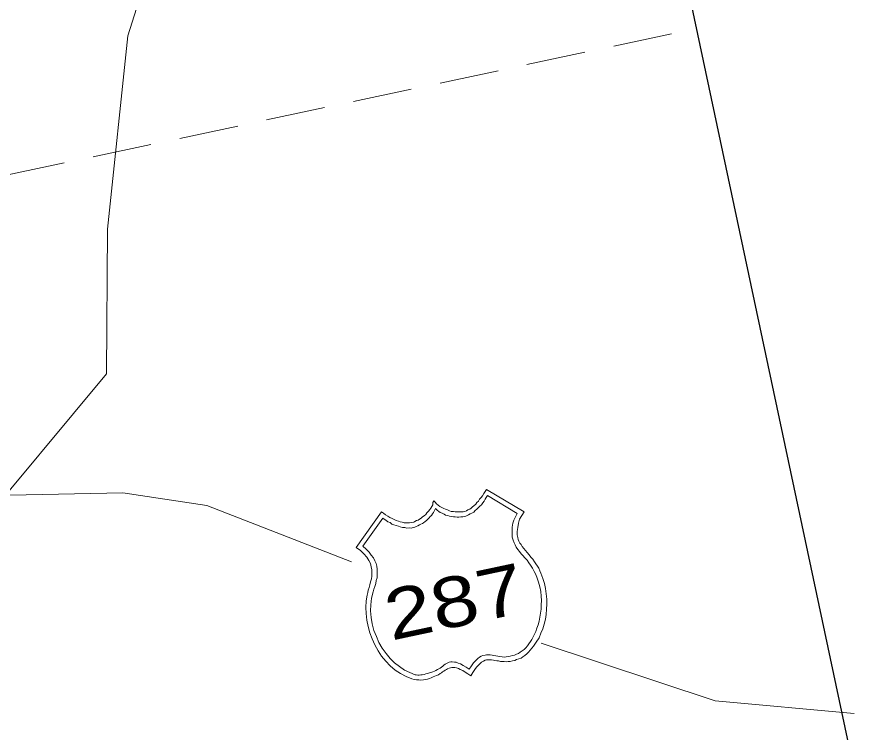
# Model space of a CAD drawing. Extents: x 2357218 to 2371708, y 6973728 to 6980157.
# Drawn here: x 2371620.9 to 2371708, y 6977470 to 6977542.6 of the extents above; entities that cross this region are included whole.
import ezdxf

# ---------------------------------------------------------------- set-up
doc = ezdxf.new("R2010")
doc.units = 0
doc.header["$LTSCALE"] = 2
doc.linetypes.add('MEDIUM_DASHED', pattern=[4.5, 3, -1.5])
doc.layers.add('62', color=7, linetype='Continuous', lineweight=13)
doc.layers.add('63', color=7, linetype='Continuous', lineweight=13)

msp = doc.modelspace()

# ---------------------------------------------------------------- linework, layer by layer
at = {"layer": '62', "linetype": 'MEDIUM_DASHED'}
msp.add_line((2371250.037, 6977447.964), (2371689.806, 6977541.441), dxfattribs=at)
at = {"layer": '62'}
for p, q in [((2371640.114, 6977493.057), (2371654.81, 6977487.347)), ((2371691.688, 6977473.263), (2371674.044, 6977479.105)), ((2371705.79, 6977471.978), (2371691.688, 6977473.263))]:
    msp.add_line(p, q, dxfattribs=at)
at = {"layer": '62', "lineweight": 25}
msp.add_lwpolyline([(2371171.482, 6977817.538), (2371268.218, 6977362.432), (2371707.985, 6977455.907), (2371611.249, 6977911.015)], dxfattribs=at)
at = {"layer": '62'}
for points in [[(2371640.114, 6977493.057), (2371631.587, 6977494.329), (2371621.782, 6977494.129), (2371604.117, 6977494.011), (2371592.783, 6977497.996), (2371585.105, 6977500.871), (2371575.158, 6977504.807), (2371564.602, 6977512.159), (2371556.475, 6977520.853), (2371548.287, 6977530.798), (2371537.195, 6977542.291), (2371528.149, 6977549.131), (2371520.811, 6977556.266), (2371512.448, 6977565.414), (2371507.538, 6977569.364), (2371497.978, 6977580.353)], [(2371641.471, 6977568.825), (2371637.889, 6977558.952), (2371632.104, 6977540.699), (2371630.059, 6977521.101), (2371629.958, 6977506.428), (2371616.354, 6977490.125), (2371618.311, 6977480.254), (2371604.289, 6977467.66), (2371593.247, 6977456.295), (2371579.034, 6977445.889), (2371557.99, 6977437.089), (2371540.234, 6977428.852), (2371521.019, 6977419.249), (2371509.386, 6977413.693)], [(2371655.262, 6977488.799), (2371657.829, 6977492.405), (2371658.044, 6977492.267), (2371658.26, 6977492.105), (2371658.491, 6977491.993), (2371658.683, 6977491.849), (2371658.917, 6977491.74), (2371659.119, 6977491.643), (2371659.323, 6977491.55), (2371659.549, 6977491.459), (2371659.722, 6977491.403), (2371659.938, 6977491.358), (2371660.133, 6977491.306), (2371660.342, 6977491.304), (2371660.528, 6977491.298), (2371660.689, 6977491.289), (2371660.911, 6977491.333), (2371661.108, 6977491.375), (2371661.232, 6977491.449), (2371661.375, 6977491.526), (2371661.546, 6977491.585), (2371661.708, 6977491.689), (2371661.872, 6977491.792), (2371662.006, 6977491.913), (2371662.17, 6977492.016), (2371662.326, 6977492.14), (2371662.452, 6977492.305), (2371662.6, 6977492.474), (2371662.727, 6977492.639), (2371662.856, 6977492.781), (2371662.934, 6977492.962), (2371663.033, 6977493.142), (2371663.058, 6977493.354), (2371663.134, 6977493.532), (2371663.276, 6977493.402), (2371663.43, 6977493.227), (2371663.598, 6977493.079), (2371663.76, 6977492.973), (2371663.947, 6977492.853), (2371664.149, 6977492.758), (2371664.327, 6977492.682), (2371664.527, 6977492.608), (2371664.724, 6977492.536), (2371664.904, 6977492.46), (2371665.133, 6977492.461), (2371665.308, 6977492.407), (2371665.558, 6977492.413), (2371665.722, 6977492.403), (2371665.95, 6977492.404), (2371666.133, 6977492.421), (2371666.285, 6977492.454), (2371666.478, 6977492.519), (2371666.597, 6977492.611), (2371666.784, 6977492.696), (2371666.947, 6977492.802), (2371667.083, 6977492.923), (2371667.219, 6977493.042), (2371667.393, 6977493.196), (2371667.52, 6977493.361), (2371667.671, 6977493.506), (2371667.792, 6977493.695), (2371667.962, 6977493.869), (2371668.086, 6977494.054), (2371668.222, 6977494.27), (2371668.339, 6977494.478), (2371668.483, 6977494.669), (2371672.298, 6977492.42), (2371672.076, 6977492.05), (2371671.855, 6977491.682), (2371671.735, 6977491.266), (2371671.667, 6977490.838), (2371671.592, 6977490.429), (2371671.594, 6977490.085), (2371671.656, 6977489.8), (2371671.698, 6977489.602), (2371671.781, 6977489.434), (2371671.889, 6977489.252), (2371671.992, 6977489.088), (2371672.126, 6977488.888), (2371672.282, 6977488.692), (2371672.441, 6977488.494), (2371672.625, 6977488.281), (2371672.808, 6977488.067), (2371672.995, 6977487.829), (2371673.18, 6977487.617), (2371673.35, 6977487.353), (2371673.511, 6977487.133), (2371673.651, 6977486.91), (2371673.79, 6977486.688), (2371673.913, 6977486.438), (2371674.007, 6977486.206), (2371674.191, 6977485.669), (2371674.376, 6977485.132), (2371674.482, 6977484.626), (2371674.527, 6977484.085), (2371674.597, 6977483.548), (2371674.612, 6977483.043), (2371674.582, 6977482.531), (2371674.53, 6977482.015), (2371674.475, 6977481.521), (2371674.353, 6977481.01)], [(2371673.346, 6977480.015), (2371673.497, 6977480.276), (2371673.609, 6977480.623), (2371673.718, 6977480.967), (2371673.824, 6977481.336), (2371673.903, 6977481.72), (2371673.978, 6977482.127), (2371674.032, 6977482.529), (2371674.05, 6977482.971), (2371674.069, 6977483.434), (2371674.023, 6977483.862), (2371673.989, 6977484.338), (2371673.894, 6977484.802), (2371673.768, 6977485.279), (2371673.634, 6977485.689), (2371673.507, 6977486.075), (2371673.328, 6977486.382), (2371673.163, 6977486.715), (2371672.966, 6977486.997), (2371672.796, 6977487.259), (2371672.602, 6977487.517), (2371672.391, 6977487.747), (2371672.182, 6977487.979), (2371672.002, 6977488.172), (2371671.841, 6977488.391), (2371671.681, 6977488.609), (2371671.513, 6977488.848), (2371671.402, 6977489.055), (2371671.283, 6977489.284), (2371671.182, 6977489.539), (2371671.095, 6977489.842), (2371671.092, 6977490.187), (2371671.088, 6977490.531), (2371671.106, 6977490.879), (2371671.162, 6977491.258), (2371671.277, 6977491.583), (2371671.438, 6977491.917), (2371671.596, 6977492.249), (2371668.587, 6977494.071), (2371668.468, 6977493.884), (2371668.366, 6977493.7), (2371668.25, 6977493.492), (2371668.124, 6977493.327), (2371667.982, 6977493.137), (2371667.828, 6977492.99), (2371667.677, 6977492.842), (2371667.522, 6977492.694), (2371667.348, 6977492.542), (2371667.195, 6977492.395), (2371667.01, 6977492.286), (2371666.845, 6977492.205), (2371666.681, 6977492.1), (2371666.533, 6977492.047), (2371666.385, 6977491.992), (2371666.234, 6977491.935), (2371666.076, 6977491.926), (2371665.894, 6977491.911), (2371665.698, 6977491.868), (2371665.532, 6977491.88), (2371665.299, 6977491.9), (2371665.135, 6977491.91), (2371664.945, 6977491.939), (2371664.729, 6977491.983), (2371664.555, 6977492.04), (2371664.339, 6977492.086), (2371664.185, 6977492.167), (2371664.002, 6977492.268), (2371663.803, 6977492.34), (2371663.639, 6977492.467), (2371663.473, 6977492.591), (2371663.304, 6977492.741), (2371663.204, 6977492.559), (2371663.11, 6977492.355), (2371663.001, 6977492.216), (2371662.896, 6977492.056), (2371662.762, 6977491.935), (2371662.674, 6977491.802), (2371662.521, 6977491.653), (2371662.409, 6977491.538), (2371662.269, 6977491.438), (2371662.111, 6977491.312), (2371661.988, 6977491.24), (2371661.822, 6977491.161), (2371661.678, 6977491.083), (2371661.537, 6977490.984), (2371661.361, 6977490.947), (2371661.218, 6977490.871), (2371661.066, 6977490.814), (2371660.847, 6977490.77), (2371660.635, 6977490.793), (2371660.409, 6977490.769), (2371660.214, 6977490.819), (2371659.98, 6977490.837), (2371659.744, 6977490.88), (2371659.564, 6977490.957), (2371659.321, 6977491.02), (2371659.096, 6977491.11), (2371658.896, 6977491.183), (2371658.702, 6977491.327), (2371658.479, 6977491.415), (2371658.285, 6977491.558)], [(2371657.966, 6977491.767), (2371655.947, 6977488.923), (2371656.287, 6977488.625), (2371656.581, 6977488.319), (2371656.805, 6977488.023), (2371657.025, 6977487.749), (2371657.16, 6977487.432), (2371657.287, 6977487.161), (2371657.365, 6977486.901), (2371657.411, 6977486.588), (2371657.406, 6977486.286), (2371657.416, 6977486.014), (2371657.385, 6977485.73), (2371657.308, 6977485.437), (2371657.256, 6977485.152), (2371657.179, 6977484.86), (2371657.078, 6977484.584), (2371656.978, 6977484.288), (2371656.813, 6977483.656), (2371656.747, 6977482.995), (2371656.719, 6977482.37), (2371656.793, 6977481.695), (2371656.907, 6977481.052), (2371657.068, 6977480.397), (2371657.319, 6977479.759), (2371657.583, 6977479.172), (2371657.911, 6977478.597), (2371658.306, 6977478.037), (2371658.733, 6977477.551), (2371659.175, 6977477.093), (2371659.668, 6977476.718), (2371660.181, 6977476.366), (2371660.718, 6977476.11), (2371661.245, 6977475.901), (2371661.363, 6977475.882), (2371661.511, 6977475.841), (2371661.669, 6977475.855), (2371661.846, 6977475.892), (2371661.981, 6977475.898), (2371662.16, 6977475.934), (2371662.336, 6977475.972), (2371662.512, 6977476.009), (2371662.705, 6977476.073), (2371662.859, 6977476.108), (2371663.046, 6977476.191), (2371663.219, 6977476.253), (2371663.364, 6977476.327), (2371663.531, 6977476.41), (2371663.671, 6977476.509), (2371663.797, 6977476.56), (2371663.912, 6977476.675), (2371664.05, 6977476.776), (2371664.148, 6977476.862), (2371664.286, 6977476.963), (2371664.432, 6977477.039), (2371664.56, 6977477.089), (2371664.704, 6977477.164), (2371664.858, 6977477.199), (2371665.022, 6977477.188), (2371665.23, 6977477.186), (2371665.414, 6977477.179), (2371665.616, 6977477.084), (2371665.867, 6977477), (2371666.133, 6977476.826), (2371666.444, 6977476.662), (2371666.743, 6977476.449), (2371666.967, 6977476.797), (2371667.18, 6977477.095), (2371667.384, 6977477.321), (2371667.595, 6977477.527), (2371667.769, 6977477.68), (2371667.958, 6977477.766), (2371668.124, 6977477.847), (2371668.345, 6977477.894), (2371668.5, 6977477.927), (2371668.662, 6977477.916), (2371668.869, 6977477.914), (2371669.059, 6977477.885), (2371669.234, 6977477.831), (2371669.422, 6977477.803), (2371669.634, 6977477.776), (2371669.852, 6977477.73), (2371670.064, 6977477.707), (2371670.273, 6977477.684), (2371670.478, 6977477.702), (2371670.699, 6977477.75), (2371670.903, 6977477.77), (2371671.118, 6977477.838), (2371671.315, 6977477.881), (2371671.525, 6977477.972), (2371671.737, 6977478.062), (2371671.92, 6977478.171), (2371672.118, 6977478.327), (2371672.296, 6977478.458), (2371672.466, 6977478.632), (2371672.659, 6977478.81), (2371672.798, 6977479.025), (2371672.953, 6977479.265), (2371673.097, 6977479.455), (2371673.221, 6977479.735), (2371673.346, 6977480.015)], [(2371658.285, 6977491.558), (2371658.126, 6977491.661), (2371657.966, 6977491.767)], [(2371656.062, 6977488.164), (2371655.718, 6977488.481), (2371655.262, 6977488.799)], [(2371674.353, 6977481.01), (2371674.199, 6977480.542), (2371673.993, 6977480.107), (2371673.818, 6977479.631), (2371673.517, 6977479.201), (2371673.263, 6977478.777), (2371672.934, 6977478.385), (2371672.745, 6977478.184), (2371672.577, 6977478.012), (2371672.378, 6977477.855), (2371672.177, 6977477.72), (2371671.999, 6977477.588), (2371671.782, 6977477.521), (2371671.549, 6977477.423), (2371671.363, 6977477.34), (2371671.118, 6977477.288), (2371670.897, 6977477.241), (2371670.697, 6977477.221), (2371670.516, 6977477.206), (2371670.283, 6977477.226), (2371670.096, 6977477.231), (2371669.91, 6977477.236), (2371669.715, 6977477.289), (2371669.527, 6977477.317), (2371669.335, 6977477.344), (2371669.19, 6977477.384), (2371669, 6977477.411), (2371668.862, 6977477.406), (2371668.677, 6977477.413), (2371668.493, 6977477.42), (2371668.342, 6977477.363), (2371668.175, 6977477.282), (2371667.991, 6977477.175), (2371667.839, 6977477.027), (2371667.664, 6977476.875), (2371667.476, 6977476.674), (2371667.299, 6977476.43), (2371667.113, 6977476.114), (2371666.909, 6977475.772), (2371666.587, 6977475.98), (2371666.323, 6977476.153), (2371666.077, 6977476.331), (2371665.825, 6977476.438), (2371665.643, 6977476.536), (2371665.448, 6977476.586), (2371665.279, 6977476.622), (2371665.117, 6977476.632), (2371664.979, 6977476.627), (2371664.825, 6977476.593), (2371664.694, 6977476.565), (2371664.55, 6977476.49), (2371664.45, 6977476.422), (2371664.299, 6977476.367), (2371664.165, 6977476.246), (2371664.041, 6977476.175), (2371663.924, 6977476.08), (2371663.779, 6977476.003), (2371663.617, 6977475.901), (2371663.427, 6977475.813), (2371663.26, 6977475.733), (2371663.067, 6977475.668), (2371662.879, 6977475.58), (2371662.714, 6977475.5), (2371662.493, 6977475.454), (2371662.293, 6977475.412), (2371662.094, 6977475.368), (2371661.844, 6977475.36), (2371661.635, 6977475.363), (2371661.402, 6977475.383), (2371661.164, 6977475.424), (2371660.919, 6977475.488), (2371660.343, 6977475.71), (2371659.769, 6977476.025), (2371659.213, 6977476.367), (2371658.732, 6977476.795), (2371658.263, 6977477.267), (2371657.856, 6977477.781), (2371657.51, 6977478.328), (2371657.175, 6977478.924), (2371656.885, 6977479.528), (2371656.661, 6977480.149), (2371656.478, 6977480.8), (2371656.34, 6977481.439), (2371656.271, 6977482.093), (2371656.252, 6977482.729), (2371656.297, 6977483.384), (2371656.399, 6977483.981), (2371656.44, 6977484.22), (2371656.498, 6977484.485), (2371656.584, 6977484.734), (2371656.66, 6977485.024), (2371656.739, 6977485.316), (2371656.812, 6977485.608), (2371656.867, 6977485.898), (2371656.871, 6977486.196), (2371656.872, 6977486.518), (2371656.803, 6977486.85), (2371656.71, 6977487.174), (2371656.551, 6977487.487), (2371656.341, 6977487.833), (2371656.062, 6977488.164)]]:
    msp.add_lwpolyline(points, dxfattribs=at)
at = {"layer": '63', "linetype": 'MEDIUM_DASHED'}
msp.add_line((2371250.037, 6977447.964), (2371689.806, 6977541.441), dxfattribs=at)
at = {"layer": '63'}
for p, q in [((2371640.114, 6977493.057), (2371654.81, 6977487.347)), ((2371691.688, 6977473.263), (2371674.044, 6977479.105)), ((2371705.79, 6977471.978), (2371691.688, 6977473.263))]:
    msp.add_line(p, q, dxfattribs=at)
at = {"layer": '63', "lineweight": 25}
msp.add_lwpolyline([(2371171.482, 6977817.538), (2371268.218, 6977362.432), (2371707.985, 6977455.907), (2371611.249, 6977911.015)], dxfattribs=at)
at = {"layer": '63'}
for points in [[(2371640.114, 6977493.057), (2371631.587, 6977494.329), (2371621.782, 6977494.129), (2371604.117, 6977494.011), (2371592.783, 6977497.996), (2371585.105, 6977500.871), (2371575.158, 6977504.807), (2371564.602, 6977512.159), (2371556.475, 6977520.853), (2371548.287, 6977530.798), (2371537.195, 6977542.291), (2371528.149, 6977549.131), (2371520.811, 6977556.266), (2371512.448, 6977565.414), (2371507.538, 6977569.364), (2371497.978, 6977580.353)], [(2371641.471, 6977568.825), (2371637.889, 6977558.952), (2371632.104, 6977540.699), (2371630.059, 6977521.101), (2371629.958, 6977506.428), (2371616.354, 6977490.125), (2371618.311, 6977480.254), (2371604.289, 6977467.66), (2371593.247, 6977456.295), (2371579.034, 6977445.889), (2371557.99, 6977437.089), (2371540.234, 6977428.852), (2371521.019, 6977419.249), (2371509.386, 6977413.693)], [(2371655.262, 6977488.799), (2371657.829, 6977492.405), (2371658.044, 6977492.267), (2371658.26, 6977492.105), (2371658.491, 6977491.993), (2371658.683, 6977491.849), (2371658.917, 6977491.74), (2371659.119, 6977491.643), (2371659.323, 6977491.55), (2371659.549, 6977491.459), (2371659.722, 6977491.403), (2371659.938, 6977491.358), (2371660.133, 6977491.306), (2371660.342, 6977491.304), (2371660.528, 6977491.298), (2371660.689, 6977491.289), (2371660.911, 6977491.333), (2371661.108, 6977491.375), (2371661.232, 6977491.449), (2371661.375, 6977491.526), (2371661.546, 6977491.585), (2371661.708, 6977491.689), (2371661.872, 6977491.792), (2371662.006, 6977491.913), (2371662.17, 6977492.016), (2371662.326, 6977492.14), (2371662.452, 6977492.305), (2371662.6, 6977492.474), (2371662.727, 6977492.639), (2371662.856, 6977492.781), (2371662.934, 6977492.962), (2371663.033, 6977493.142), (2371663.058, 6977493.354), (2371663.134, 6977493.532), (2371663.276, 6977493.402), (2371663.43, 6977493.227), (2371663.598, 6977493.079), (2371663.76, 6977492.973), (2371663.947, 6977492.853), (2371664.149, 6977492.758), (2371664.327, 6977492.682), (2371664.527, 6977492.608), (2371664.724, 6977492.536), (2371664.904, 6977492.46), (2371665.133, 6977492.461), (2371665.308, 6977492.407), (2371665.558, 6977492.413), (2371665.722, 6977492.403), (2371665.95, 6977492.404), (2371666.133, 6977492.421), (2371666.285, 6977492.454), (2371666.478, 6977492.519), (2371666.597, 6977492.611), (2371666.784, 6977492.696), (2371666.947, 6977492.802), (2371667.083, 6977492.923), (2371667.219, 6977493.042), (2371667.393, 6977493.196), (2371667.52, 6977493.361), (2371667.671, 6977493.506), (2371667.792, 6977493.695), (2371667.962, 6977493.869), (2371668.086, 6977494.054), (2371668.222, 6977494.27), (2371668.339, 6977494.478), (2371668.483, 6977494.669), (2371672.298, 6977492.42), (2371672.076, 6977492.05), (2371671.855, 6977491.682), (2371671.735, 6977491.266), (2371671.667, 6977490.838), (2371671.592, 6977490.429), (2371671.594, 6977490.085), (2371671.656, 6977489.8), (2371671.698, 6977489.602), (2371671.781, 6977489.434), (2371671.889, 6977489.252), (2371671.992, 6977489.088), (2371672.126, 6977488.888), (2371672.282, 6977488.692), (2371672.441, 6977488.494), (2371672.625, 6977488.281), (2371672.808, 6977488.067), (2371672.995, 6977487.829), (2371673.18, 6977487.617), (2371673.35, 6977487.353), (2371673.511, 6977487.133), (2371673.651, 6977486.91), (2371673.79, 6977486.688), (2371673.913, 6977486.438), (2371674.007, 6977486.206), (2371674.191, 6977485.669), (2371674.376, 6977485.132), (2371674.482, 6977484.626), (2371674.527, 6977484.085), (2371674.597, 6977483.548), (2371674.612, 6977483.043), (2371674.582, 6977482.531), (2371674.53, 6977482.015), (2371674.475, 6977481.521), (2371674.353, 6977481.01)], [(2371673.346, 6977480.015), (2371673.497, 6977480.276), (2371673.609, 6977480.623), (2371673.718, 6977480.967), (2371673.824, 6977481.336), (2371673.903, 6977481.72), (2371673.978, 6977482.127), (2371674.032, 6977482.529), (2371674.05, 6977482.971), (2371674.069, 6977483.434), (2371674.023, 6977483.862), (2371673.989, 6977484.338), (2371673.894, 6977484.802), (2371673.768, 6977485.279), (2371673.634, 6977485.689), (2371673.507, 6977486.075), (2371673.328, 6977486.382), (2371673.163, 6977486.715), (2371672.966, 6977486.997), (2371672.796, 6977487.259), (2371672.602, 6977487.517), (2371672.391, 6977487.747), (2371672.182, 6977487.979), (2371672.002, 6977488.172), (2371671.841, 6977488.391), (2371671.681, 6977488.609), (2371671.513, 6977488.848), (2371671.402, 6977489.055), (2371671.283, 6977489.284), (2371671.182, 6977489.539), (2371671.095, 6977489.842), (2371671.092, 6977490.187), (2371671.088, 6977490.531), (2371671.106, 6977490.879), (2371671.162, 6977491.258), (2371671.277, 6977491.583), (2371671.438, 6977491.917), (2371671.596, 6977492.249), (2371668.587, 6977494.071), (2371668.468, 6977493.884), (2371668.366, 6977493.7), (2371668.25, 6977493.492), (2371668.124, 6977493.327), (2371667.982, 6977493.137), (2371667.828, 6977492.99), (2371667.677, 6977492.842), (2371667.522, 6977492.694), (2371667.348, 6977492.542), (2371667.195, 6977492.395), (2371667.01, 6977492.286), (2371666.845, 6977492.205), (2371666.681, 6977492.1), (2371666.533, 6977492.047), (2371666.385, 6977491.992), (2371666.234, 6977491.935), (2371666.076, 6977491.926), (2371665.894, 6977491.911), (2371665.698, 6977491.868), (2371665.532, 6977491.88), (2371665.299, 6977491.9), (2371665.135, 6977491.91), (2371664.945, 6977491.939), (2371664.729, 6977491.983), (2371664.555, 6977492.04), (2371664.339, 6977492.086), (2371664.185, 6977492.167), (2371664.002, 6977492.268), (2371663.803, 6977492.34), (2371663.639, 6977492.467), (2371663.473, 6977492.591), (2371663.304, 6977492.741), (2371663.204, 6977492.559), (2371663.11, 6977492.355), (2371663.001, 6977492.216), (2371662.896, 6977492.056), (2371662.762, 6977491.935), (2371662.674, 6977491.802), (2371662.521, 6977491.653), (2371662.409, 6977491.538), (2371662.269, 6977491.438), (2371662.111, 6977491.312), (2371661.988, 6977491.24), (2371661.822, 6977491.161), (2371661.678, 6977491.083), (2371661.537, 6977490.984), (2371661.361, 6977490.947), (2371661.218, 6977490.871), (2371661.066, 6977490.814), (2371660.847, 6977490.77), (2371660.635, 6977490.793), (2371660.409, 6977490.769), (2371660.214, 6977490.819), (2371659.98, 6977490.837), (2371659.744, 6977490.88), (2371659.564, 6977490.957), (2371659.321, 6977491.02), (2371659.096, 6977491.11), (2371658.896, 6977491.183), (2371658.702, 6977491.327), (2371658.479, 6977491.415), (2371658.285, 6977491.558)], [(2371657.966, 6977491.767), (2371655.947, 6977488.923), (2371656.287, 6977488.625), (2371656.581, 6977488.319), (2371656.805, 6977488.023), (2371657.025, 6977487.749), (2371657.16, 6977487.432), (2371657.287, 6977487.161), (2371657.365, 6977486.901), (2371657.411, 6977486.588), (2371657.406, 6977486.286), (2371657.416, 6977486.014), (2371657.385, 6977485.73), (2371657.308, 6977485.437), (2371657.256, 6977485.152), (2371657.179, 6977484.86), (2371657.078, 6977484.584), (2371656.978, 6977484.288), (2371656.813, 6977483.656), (2371656.747, 6977482.995), (2371656.719, 6977482.37), (2371656.793, 6977481.695), (2371656.907, 6977481.052), (2371657.068, 6977480.397), (2371657.319, 6977479.759), (2371657.583, 6977479.172), (2371657.911, 6977478.597), (2371658.306, 6977478.037), (2371658.733, 6977477.551), (2371659.175, 6977477.093), (2371659.668, 6977476.718), (2371660.181, 6977476.366), (2371660.718, 6977476.11), (2371661.245, 6977475.901), (2371661.363, 6977475.882), (2371661.511, 6977475.841), (2371661.669, 6977475.855), (2371661.846, 6977475.892), (2371661.981, 6977475.898), (2371662.16, 6977475.934), (2371662.336, 6977475.972), (2371662.512, 6977476.009), (2371662.705, 6977476.073), (2371662.859, 6977476.108), (2371663.046, 6977476.191), (2371663.219, 6977476.253), (2371663.364, 6977476.327), (2371663.531, 6977476.41), (2371663.671, 6977476.509), (2371663.797, 6977476.56), (2371663.912, 6977476.675), (2371664.05, 6977476.776), (2371664.148, 6977476.862), (2371664.286, 6977476.963), (2371664.432, 6977477.039), (2371664.56, 6977477.089), (2371664.704, 6977477.164), (2371664.858, 6977477.199), (2371665.022, 6977477.188), (2371665.23, 6977477.186), (2371665.414, 6977477.179), (2371665.616, 6977477.084), (2371665.867, 6977477), (2371666.133, 6977476.826), (2371666.444, 6977476.662), (2371666.743, 6977476.449), (2371666.967, 6977476.797), (2371667.18, 6977477.095), (2371667.384, 6977477.321), (2371667.595, 6977477.527), (2371667.769, 6977477.68), (2371667.958, 6977477.766), (2371668.124, 6977477.847), (2371668.345, 6977477.894), (2371668.5, 6977477.927), (2371668.662, 6977477.916), (2371668.869, 6977477.914), (2371669.059, 6977477.885), (2371669.234, 6977477.831), (2371669.422, 6977477.803), (2371669.634, 6977477.776), (2371669.852, 6977477.73), (2371670.064, 6977477.707), (2371670.273, 6977477.684), (2371670.478, 6977477.702), (2371670.699, 6977477.75), (2371670.903, 6977477.77), (2371671.118, 6977477.838), (2371671.315, 6977477.881), (2371671.525, 6977477.972), (2371671.737, 6977478.062), (2371671.92, 6977478.171), (2371672.118, 6977478.327), (2371672.296, 6977478.458), (2371672.466, 6977478.632), (2371672.659, 6977478.81), (2371672.798, 6977479.025), (2371672.953, 6977479.265), (2371673.097, 6977479.455), (2371673.221, 6977479.735), (2371673.346, 6977480.015)], [(2371658.285, 6977491.558), (2371658.126, 6977491.661), (2371657.966, 6977491.767)], [(2371656.062, 6977488.164), (2371655.718, 6977488.481), (2371655.262, 6977488.799)], [(2371674.353, 6977481.01), (2371674.199, 6977480.542), (2371673.993, 6977480.107), (2371673.818, 6977479.631), (2371673.517, 6977479.201), (2371673.263, 6977478.777), (2371672.934, 6977478.385), (2371672.745, 6977478.184), (2371672.577, 6977478.012), (2371672.378, 6977477.855), (2371672.177, 6977477.72), (2371671.999, 6977477.588), (2371671.782, 6977477.521), (2371671.549, 6977477.423), (2371671.363, 6977477.34), (2371671.118, 6977477.288), (2371670.897, 6977477.241), (2371670.697, 6977477.221), (2371670.516, 6977477.206), (2371670.283, 6977477.226), (2371670.096, 6977477.231), (2371669.91, 6977477.236), (2371669.715, 6977477.289), (2371669.527, 6977477.317), (2371669.335, 6977477.344), (2371669.19, 6977477.384), (2371669, 6977477.411), (2371668.862, 6977477.406), (2371668.677, 6977477.413), (2371668.493, 6977477.42), (2371668.342, 6977477.363), (2371668.175, 6977477.282), (2371667.991, 6977477.175), (2371667.839, 6977477.027), (2371667.664, 6977476.875), (2371667.476, 6977476.674), (2371667.299, 6977476.43), (2371667.113, 6977476.114), (2371666.909, 6977475.772), (2371666.587, 6977475.98), (2371666.323, 6977476.153), (2371666.077, 6977476.331), (2371665.825, 6977476.438), (2371665.643, 6977476.536), (2371665.448, 6977476.586), (2371665.279, 6977476.622), (2371665.117, 6977476.632), (2371664.979, 6977476.627), (2371664.825, 6977476.593), (2371664.694, 6977476.565), (2371664.55, 6977476.49), (2371664.45, 6977476.422), (2371664.299, 6977476.367), (2371664.165, 6977476.246), (2371664.041, 6977476.175), (2371663.924, 6977476.08), (2371663.779, 6977476.003), (2371663.617, 6977475.901), (2371663.427, 6977475.813), (2371663.26, 6977475.733), (2371663.067, 6977475.668), (2371662.879, 6977475.58), (2371662.714, 6977475.5), (2371662.493, 6977475.454), (2371662.293, 6977475.412), (2371662.094, 6977475.368), (2371661.844, 6977475.36), (2371661.635, 6977475.363), (2371661.402, 6977475.383), (2371661.164, 6977475.424), (2371660.919, 6977475.488), (2371660.343, 6977475.71), (2371659.769, 6977476.025), (2371659.213, 6977476.367), (2371658.732, 6977476.795), (2371658.263, 6977477.267), (2371657.856, 6977477.781), (2371657.51, 6977478.328), (2371657.175, 6977478.924), (2371656.885, 6977479.528), (2371656.661, 6977480.149), (2371656.478, 6977480.8), (2371656.34, 6977481.439), (2371656.271, 6977482.093), (2371656.252, 6977482.729), (2371656.297, 6977483.384), (2371656.399, 6977483.981), (2371656.44, 6977484.22), (2371656.498, 6977484.485), (2371656.584, 6977484.734), (2371656.66, 6977485.024), (2371656.739, 6977485.316), (2371656.812, 6977485.608), (2371656.867, 6977485.898), (2371656.871, 6977486.196), (2371656.872, 6977486.518), (2371656.803, 6977486.85), (2371656.71, 6977487.174), (2371656.551, 6977487.487), (2371656.341, 6977487.833), (2371656.062, 6977488.164)]]:
    msp.add_lwpolyline(points, dxfattribs=at)

# ---------------------------------------------------------------- texts
at = {"layer": '62', "width": 1.25}
msp.add_text('287', height=5.099, rotation=12, dxfattribs=at).set_placement((2371658.812, 6977479.342))
at = {"layer": '63', "width": 1.25}
msp.add_text('287', height=5.099, rotation=12, dxfattribs=at).set_placement((2371658.812, 6977479.342))

doc.saveas('drawing.dxf')
